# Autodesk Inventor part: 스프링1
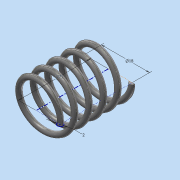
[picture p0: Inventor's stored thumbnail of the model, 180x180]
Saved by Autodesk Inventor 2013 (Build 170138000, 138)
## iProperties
Created: 2016-10
Part Number: 스프링1
Material: 강철, 탄소
Document SubType Name: Modeling
Designer: user
Mass: 6.88075 g
Surface Area: 17.7314 cm^2
Volume: 0.874302 cm^3
Density: 7.87 g/cm^3
Author: user
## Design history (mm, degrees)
sketch "스케치1"
  geometry: L1 (0, 0)-(9, 0); L2 (9, 0)-(9, 16.67); L3 (9, 16.67)-(0, 16.67); L4 (0, 16.67)-(0, 0); C1 r 1 at (9, 0)
  constraints: 8 end point, 2 parallel, 1 centre point, 1 coincident, 1 horizontal, 1 perpendicular
  dimensions: "d0" = 16.66987 distance of L3.end L1.start (derived); "d1" = 18 diameter of L2 L4; "d2" = 2 diameter of C1
feature "코일1" pitch "d3" = 10; turns "d5" = 5; dims "d4" = 16.66987 (= d0), "d6" = 0, angle "d7" = 90 deg, angle "d8" = 90 deg, "d9" = 0, "d10" = 0
sketch "스케치2"
  geometry: L1 (-8, 0)-(-10, 0) reference; 1 further point
  constraints: 1 horizontal alignment
extrude "돌출1" cut sketch "스케치2" distance "d11" = 10; taper "d12" = 0 deg
node "작업 평면1"
sketch "스케치3"
  geometry: L1 (-1, 0)-(1, 0) reference; 1 further point
  constraints: 1 horizontal alignment
extrude "돌출2" cut sketch "스케치3" distance "d14" = 10; taper "d15" = 0 deg
node "솔리드1"
node "절단 모서리 투영1"
node "절단 모서리 투영2"
other parameters: "d13" = 0
